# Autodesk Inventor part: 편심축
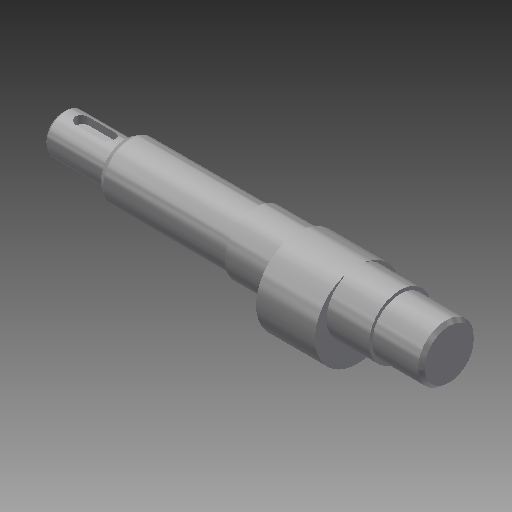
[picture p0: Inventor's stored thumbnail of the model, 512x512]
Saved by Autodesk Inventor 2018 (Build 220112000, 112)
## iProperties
Created: 2017-08
Part Number: 편심축
Material: 강철, 연강
Document SubType Name: Modeling
Designer: mduedu
Density: 1 g/cm^3
Appearance: 강철
Author: mduedu
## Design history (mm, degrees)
sketch "스케치1"
  geometry: L1 (0, 0)-(118, 0); L2 (118, 0)-(118, 8.5); L3 (118, 8.5)-(103, 8.5); L4 (103, 8.5)-(103, 9.5); L5 (103, 9.5)-(59, 9.5); L6 (59, 9.5)-(59, 8.5); L7 (59, 8.5)-(19, 8.5); L8 (19, 8.5)-(19, 6); L9 (19, 6)-(0, 6); L10 (0, 6)-(0, 0)
  constraints: 20 end point, 6 parallel, 2 collinear, 2 perpendicular, 1 horizontal
  dimensions: "d0" = 118 distance of L1.start L1.end; "d1" = 17 diameter of L3 L1; "d2" = 19 diameter of L5 L1; "d3" = 12 diameter of L9 L1; "d4" = 19 distance of L8.end L9.end; "d5" = 15 distance of L2.end L3.end; "d6" = 44 distance of L4.end L5.end
revolve "회전1" sketch "스케치1" stored, may be unused: angle "d7" = 90 deg
node "작업 평면1"
sketch "스케치2"
  geometry: C1 r 9.5 at (0, 0) reference; C2 r 13 at (0, -3.5); 1 further point
  constraints: 1 centre point, 1 tangent, 1 vertical alignment
  dimensions: "d8" = 3.5 distance of point (0, 0) C2.centre
extrude "돌출1" join sketch "스케치2" stored distance "d9" = 18; taper "d10" = 0 deg
chamfer "모따기1" distance "d11" = 1; stored, may be unused: second distance "d12" = 2, angle "d13" = 45 deg
node "작업 평면2"
sketch "스케치3"
  geometry: L1 (3.5, -2)-(-4.5, -2); L2 (-4.5, -2)-(-4.5, 2); L3 (-4.5, 2)-(3.5, 2); L4 (3.5, 2)-(3.5, -2); L5 (9.5, 6)-(9.5, -6) reference; A1 r 2 centre (3.5, 0) between (3.5, -2) and (3.5, 2); A2 r 2 centre (-4.5, 0) between (-4.5, 2) and (-4.5, -2); A3 r 2 centre (3.5, 0) between (3.5, 2) and (3.5, -2); A4 r 2 centre (-4.5, 0) between (-4.5, -2) and (-4.5, 2); 1 further point
  constraints: 8 end point, 8 point on circle, 4 centre point, 2 midpoint, 2 parallel, 1 horizontal, 1 horizontal alignment, 1 perpendicular
  dimensions: "d14" = 12 dimension on A2 A1; "d16" = 4 distance between parallel lines of L3 L1; "d17" = 4 distance edge to line of A1 L5
extrude "돌출2" cut sketch "스케치3" distance "d18" = 2.5; taper "d19" = 0 deg
chamfer "모따기2" distance "d20" = 1; stored, may be unused: second distance "d21" = 2, angle "d22" = 45 deg
chamfer "모따기3" distance "d23" = 1; stored, may be unused: second distance "d24" = 2, angle "d25" = 60 deg
fillet "모깎기1" dims "d26" = 0.5
hole "구멍1" diameter "d29" = 3.242; stored, may be unused: countersink angle "d33" = 90 deg, drill point angle "d35" = 118 deg; dims "d30" = 8, "d31" = 4, "d32" = 2, "d34" = 10, "d36" = 10, "d37" = 10
node "솔리드1"
node "절단 모서리 투영1"
